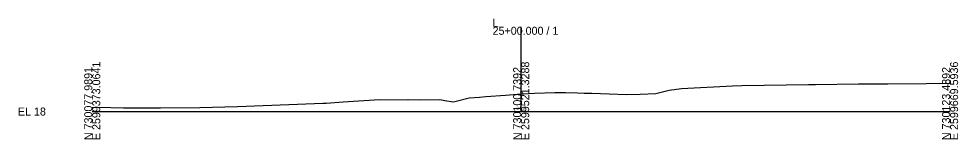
# Model space of a CAD drawing. Extents: x -26 to 3303, y -10 to 9555.
# Drawn here: x 2974.3 to 3302.8, y -9.7 to 32.5 of the extents above; entities that cross this region are included whole.
import ezdxf

# ---------------------------------------------------------------- set-up
doc = ezdxf.new("R2010")
doc.units = 0
for name, color, linetype in [('Exist Cross Section Cell', 7, 'Continuous'), ('Exist XS Center Line Elevation Label', 7, 'Continuous'), ('Exist XS Ground Line', 7, 'Continuous')]:
    doc.layers.add(name, color=color, linetype=linetype)

msp = doc.modelspace()

# ---------------------------------------------------------------- linework, layer by layer
at = {"layer": 'Exist Cross Section Cell'}
for p, q in [((3150, 0), (3150, 29.69)), ((3000, 0), (3150, 0)), ((3150, 0), (3300, 0))]:
    msp.add_line(p, q, dxfattribs=at)
at = {"layer": 'Exist XS Ground Line'}
msp.add_lwpolyline([(3000, 1.42), (3001.97, 1.55), (3010.98, 1.36), (3023.87, 1.35), (3037.65, 1.42), (3050.74, 1.74), (3077.7, 2.81), (3080.67, 2.91), (3081.77, 2.96), (3087.77, 3.35), (3100.5, 4.23), (3110.28, 4.14), (3110.74, 4.17), (3114.29, 4.12), (3121.56, 4.17), (3123.29, 3.88), (3126.19, 3.35), (3127.22, 3.61), (3131.87, 4.77), (3135.43, 5.04), (3137.63, 5.23), (3144.52, 5.76), (3150, 6.16), (3150.77, 6.22), (3154.61, 6.4), (3161.81, 6.68), (3165.53, 6.67), (3169.67, 6.55), (3172.03, 6.47), (3174.74, 6.42), (3180.79, 6.15), (3186.92, 6.02), (3191.57, 6.04), (3197.13, 6.32), (3201.74, 7.46), (3206.12, 8.11), (3223.93, 9), (3227.22, 9.1), (3250.44, 9.46), (3252.38, 9.5), (3252.92, 9.51), (3267.95, 9.7), (3276.44, 9.76), (3278.27, 9.76), (3291.58, 9.88), (3300, 9.9)], dxfattribs=at)

# ---------------------------------------------------------------- texts
at = {"layer": 'Exist Cross Section Cell'}
for s, p in [('25+00.000 / 1', (3140, 26.89)), ('L', (3140, 29.69)), ('EL 18', (2974, -1.4))]:
    msp.add_text(s, height=2.8, dxfattribs=at).set_placement(p)
for s, p in [('E 2599373.0641', (3002.8, -10)), ('E 2599521.3288', (3152.8, -10)), ('E 2599669.5936', (3302.8, -10)), ('N 730077.9891', (3000, -10)), ('N 730100.7392', (3150, -10)), ('N 730123.4892', (3300, -10))]:
    msp.add_text(s, height=2.8, rotation=90, dxfattribs=at).set_placement(p)
at = {"layer": 'Exist XS Center Line Elevation Label'}
msp.add_text('24.16', height=1, dxfattribs=at).set_placement((3148.38, 0.66))

doc.saveas('drawing.dxf')
